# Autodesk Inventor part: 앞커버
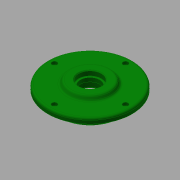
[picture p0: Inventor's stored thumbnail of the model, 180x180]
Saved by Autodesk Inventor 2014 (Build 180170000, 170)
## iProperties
Created: 2016-11
Part Number: 앞커버
Material: 알루미늄 6061
Document SubType Name: Modeling
Designer: mduedu
Density: 1 g/cm^3
Mass: 188.69 g
Surface Area: 365.029 cm^2
Volume: 188.69 cm^3
Appearance: 진녹색
Author: mduedu
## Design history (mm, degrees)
sketch "스케치1"
  geometry: L1 (28.5, -17.5)-(28.5, -30); L2 (28.5, -30)-(22.5, -33.464); L3 (22.5, -33.464)-(22.5, -65); L4 (22.5, -65)-(14.5, -65); L5 (14.5, -65)-(14.5, -47.5); L6 (14.5, -47.5)-(0, -47.5); L7 (0, -47.5)-(0, -23.5); L8 (0, 0)-(28.5, 0); L9 (14.5, -23.5)-(14.5, -15); L10 (14.5, -15)-(20.5, -15); L11 (20.5, -15)-(20.5, -17.5); L12 (0, -23.5)-(14.5, -23.5); L13 (20.5, -17.5)-(28.5, -17.5)
  constraints: 26 end point, 8 parallel, 3 perpendicular, 2 horizontal, 2 vertical alignment, 1 collinear
  dimensions: "d0" = 14.5 distance of L5.end L6.end; "d2" = 8 distance of L3.end L4.end; "d3" = 6 distance between parallel lines of L1 L3; "d4" = 120 deg angle of L3 L2; "d5" = 8 distance of L11.end L1.start; "d6" = 60 diameter of L1.end L8; "d7" = 30 diameter of L10 L8; "d8" = 47 diameter of L12 L8; "d9" = 35 diameter of L13 L8; "d10" = 95 diameter of L6 L8; "d11" = 130 diameter of L4 L8
revolve "회전1" sketch "스케치1" stored, may be unused: angle "d12" = 90 deg
fillet "모깎기1" dims "d13" = 0.5
fillet "모깎기2" dims "d14" = 3
chamfer "모따기1" distance "d15" = 1; stored, may be unused: second distance "d16" = 2, angle "d17" = 45 deg
fillet "모깎기3" dims "d18" = 0.3
sketch "스케치2" dims "d19" = 110
  geometry: 6 further points
  constraints: 2 vertical alignment, 1 coincident, 7 other
  dimensions: "d22" = 360 deg dimension on point (0, 0) point (0, 55) (derived)
sketch "스케치3"
  geometry: 4 further points
  constraints: 4 other
hole "구멍1" sketch "스케치3" at (0, 55), (-55, 0), (55, 0), (0, -55) diameter "d24" = 4.5; stored, may be unused: countersink angle "d28" = 90 deg, drill point angle "d30" = 0 deg; dims "d25" = 6, "d26" = 8, "d27" = 4.6, "d29" = 8
node "솔리드1"
